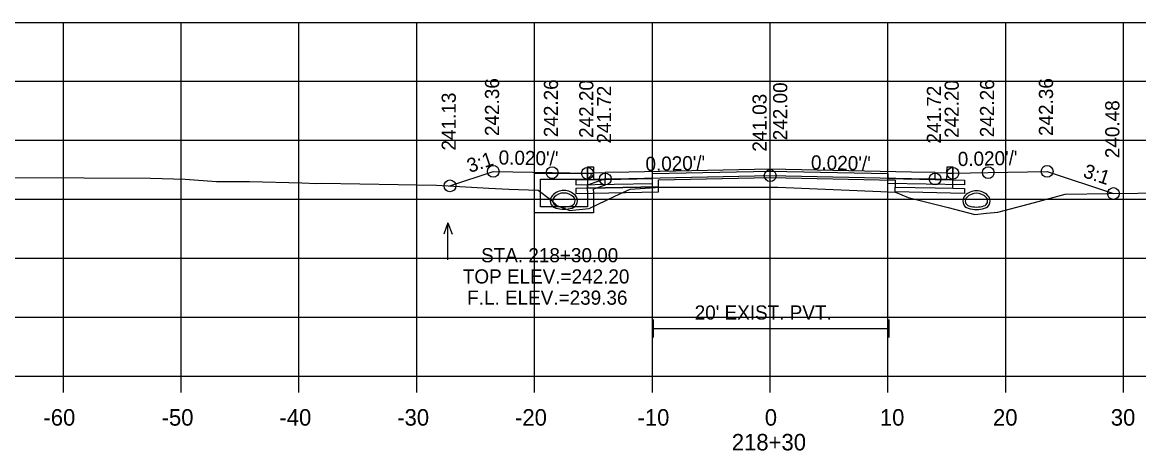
# Model space of a CAD drawing. Extents: x 1369627 to 1374022, y 380035 to 398173.
# Drawn here: x 1371475.4 to 1371570.1, y 384109.9 to 384146.2 of the extents above; entities that cross this region are included whole.
import ezdxf

# ---------------------------------------------------------------- set-up
doc = ezdxf.new("R2010")
doc.units = 0
for name, color, linetype in [('Default', 7, 'Continuous'), ('R_Alt Surface', 7, 'Continuous'), ('R_Axis', 7, 'Continuous'), ('R_Axis Annot', 7, 'Continuous'), ('R_Drive', 7, 'Continuous'), ('R_Exist Surface', 7, 'Continuous'), ('R_Fin Surface', 7, 'Continuous'), ('R_Grid', 7, 'Continuous'), ('R_No Plot', 7, 'Continuous'), ('R_Water', 7, 'Continuous'), ('R_Water Annot', 7, 'Continuous'), ('R_Xsect Elev', 7, 'Continuous'), ('R_Xsect Slope', 7, 'Continuous')]:
    doc.layers.add(name, color=color, linetype=linetype)

msp = doc.modelspace()

# ---------------------------------------------------------------- linework, layer by layer
at = {"layer": 'Default'}
for p, q in [((1371528.933, 384119.469), (1371528.933, 384120.969)), ((1371548.933, 384119.469), (1371548.933, 384120.969)), ((1371528.933, 384120.219), (1371548.933, 384120.219))]:
    msp.add_line(p, q, dxfattribs=at)
for points in [[(1371523.336, 384133.923), (1371523.836, 384133.923), (1371523.846, 384133.423), (1371524.846, 384133.443), (1371524.846, 384132.856), (1371523.346, 384132.826)], [(1371553.846, 384133.423), (1371553.856, 384133.923), (1371554.356, 384133.923), (1371554.346, 384132.826), (1371552.846, 384132.856), (1371552.846, 384133.443)]]:
    msp.add_lwpolyline(points, close=True, dxfattribs=at)
at = {"layer": 'R_Alt Surface'}
for points in [[(1371523.336, 384133.923), (1371523.346, 384132.826), (1371524.846, 384132.856), (1371528.846, 384132.936), (1371528.846, 384133.353), (1371538.846, 384133.553), (1371548.846, 384133.353), (1371548.846, 384132.936), (1371552.846, 384132.856), (1371554.346, 384132.826), (1371554.356, 384133.923)], [(1371523.336, 384133.381), (1371523.346, 384132.118), (1371524.846, 384132.148), (1371529.358, 384132.238), (1371529.358, 384132.821), (1371538.846, 384133.011), (1371549.468, 384132.798), (1371549.468, 384132.215), (1371552.846, 384132.148), (1371554.346, 384132.118), (1371554.356, 384133.381)]]:
    msp.add_lwpolyline(points, dxfattribs=at)
for points in [[(1371538.846, 384133.723), (1371526.846, 384133.483), (1371524.846, 384133.443), (1371524.846, 384132.856), (1371528.846, 384132.936), (1371528.846, 384133.353), (1371538.846, 384133.553), (1371548.846, 384133.353), (1371548.846, 384132.936), (1371552.846, 384132.856), (1371552.846, 384133.443), (1371550.846, 384133.483)], [(1371528.846, 384132.936), (1371524.846, 384132.856), (1371523.346, 384132.826), (1371522.346, 384132.806), (1371522.346, 384132.389), (1371528.846, 384132.519)], [(1371529.358, 384132.238), (1371524.846, 384132.148), (1371523.346, 384132.118), (1371522.346, 384132.098), (1371522.346, 384131.681), (1371529.358, 384131.821)], [(1371548.846, 384132.936), (1371552.846, 384132.856), (1371554.346, 384132.826), (1371555.346, 384132.806), (1371555.346, 384132.389), (1371548.846, 384132.519)], [(1371549.468, 384132.215), (1371552.846, 384132.148), (1371554.346, 384132.118), (1371555.346, 384132.098), (1371555.346, 384131.681), (1371549.468, 384131.798)]]:
    msp.add_lwpolyline(points, close=True, dxfattribs=at)
at = {"layer": 'R_Axis'}
for p, q in [((1371388.846, 384116.181), (1371688.846, 384116.181)), ((1371478.846, 384114.781), (1371478.846, 384116.181)), ((1371488.846, 384114.781), (1371488.846, 384116.181)), ((1371498.846, 384114.781), (1371498.846, 384116.181)), ((1371508.846, 384114.781), (1371508.846, 384116.181)), ((1371518.846, 384114.781), (1371518.846, 384116.181)), ((1371528.846, 384114.781), (1371528.846, 384116.181)), ((1371538.846, 384114.781), (1371538.846, 384116.181)), ((1371548.846, 384114.781), (1371548.846, 384116.181)), ((1371558.846, 384114.781), (1371558.846, 384116.181)), ((1371568.846, 384114.781), (1371568.846, 384116.181))]:
    msp.add_line(p, q, dxfattribs=at)
at = {"layer": 'R_Drive'}
for centre, radius, start, end in [((1371520.823, 384131.05), 0.646, 136.35152, 253.95293), ((1371520.823, 384131.05), 0.646, 136.35152, 253.95293), ((1371521.336, 384130.561), 1.354, 43.64848, 136.35152), ((1371521.336, 384130.561), 1.354, 43.64848, 136.35152), ((1371520.823, 384131.05), 0.438, 136.35152, 253.95293), ((1371520.823, 384131.05), 0.438, 136.35152, 253.95293), ((1371521.336, 384130.561), 1.146, 43.64848, 136.35152), ((1371521.336, 384130.561), 1.146, 43.64848, 136.35152), ((1371521.848, 384131.05), 0.438, 286.04707, 43.64848), ((1371521.848, 384131.05), 0.438, 286.04707, 43.64848), ((1371521.848, 384131.05), 0.646, 286.04707, 43.64848), ((1371521.848, 384131.05), 0.646, 286.04707, 43.64848), ((1371555.843, 384131.031), 0.646, 136.35152, 253.95293), ((1371556.356, 384130.542), 1.354, 43.64848, 136.35152), ((1371555.843, 384131.031), 0.438, 136.35152, 253.95293), ((1371556.356, 384130.542), 1.146, 43.64848, 136.35152), ((1371556.868, 384131.031), 0.438, 286.04707, 43.64848), ((1371556.868, 384131.031), 0.646, 286.04707, 43.64848), ((1371521.336, 384132.832), 2.5, 253.95293, 286.04707), ((1371521.336, 384132.832), 2.5, 253.95293, 286.04707), ((1371521.336, 384132.832), 2.292, 253.95293, 286.04707), ((1371521.336, 384132.832), 2.292, 253.95293, 286.04707), ((1371556.356, 384132.813), 2.5, 253.95293, 286.04707), ((1371556.356, 384132.813), 2.292, 253.95293, 286.04707)]:
    msp.add_arc(centre, radius, start, end, dxfattribs=at)
at = {"layer": 'R_Exist Surface'}
msp.add_lwpolyline([(1371460.93, 384133.052), (1371480.608, 384132.995), (1371486.239, 384132.978), (1371489.193, 384132.892), (1371491.852, 384132.675), (1371494.248, 384132.694), (1371494.651, 384132.687), (1371499.078, 384132.571), (1371500.357, 384132.52), (1371500.761, 384132.53), (1371510.527, 384132.38), (1371514.966, 384132.129), (1371516.65, 384132.025), (1371519.149, 384131.96), (1371520.194, 384131.15), (1371520.736, 384130.637), (1371521.706, 384130.269), (1371521.815, 384130.227), (1371522.351, 384130.286), (1371523.471, 384130.394), (1371525.668, 384131.437), (1371526.954, 384132.045), (1371529.096, 384132.177), (1371529.358, 384132.202), (1371530.403, 384132.206), (1371539.505, 384132.212), (1371548.246, 384131.832), (1371549.468, 384131.779), (1371549.48, 384131.774), (1371550.556, 384131.333), (1371553.949, 384130.473), (1371556.22, 384129.89), (1371557.22, 384129.988), (1371558.178, 384130.085), (1371561.283, 384130.916), (1371563.876, 384131.601), (1371567.587, 384131.659), (1371574.957, 384131.752)], dxfattribs=at)
at = {"layer": 'R_Fin Surface'}
msp.add_lwpolyline([(1371511.66, 384132.316), (1371515.336, 384133.541), (1371520.336, 384133.441), (1371523.336, 384133.381), (1371523.836, 384133.381), (1371523.846, 384132.881), (1371524.846, 384132.901), (1371526.846, 384132.941), (1371538.846, 384133.181), (1371550.846, 384132.941), (1371552.846, 384132.901), (1371553.846, 384132.881), (1371553.856, 384133.381), (1371554.356, 384133.381), (1371557.356, 384133.441), (1371562.356, 384133.541), (1371567.988, 384131.664)], dxfattribs=at)
at = {"layer": 'R_Grid'}
for p, q in [((1371388.846, 384146.181), (1371688.846, 384146.181)), ((1371478.846, 384116.181), (1371478.846, 384146.181)), ((1371488.846, 384116.181), (1371488.846, 384146.181)), ((1371498.846, 384116.181), (1371498.846, 384146.181)), ((1371508.846, 384116.181), (1371508.846, 384146.181)), ((1371518.846, 384116.181), (1371518.846, 384146.181)), ((1371528.846, 384116.181), (1371528.846, 384146.181)), ((1371538.846, 384116.181), (1371538.846, 384146.181)), ((1371548.846, 384116.181), (1371548.846, 384146.181)), ((1371558.846, 384116.181), (1371558.846, 384146.181)), ((1371568.846, 384116.181), (1371568.846, 384146.181)), ((1371388.846, 384141.181), (1371688.846, 384141.181)), ((1371388.846, 384136.181), (1371688.846, 384136.181)), ((1371388.846, 384131.181), (1371688.846, 384131.181)), ((1371388.846, 384126.181), (1371688.846, 384126.181)), ((1371388.846, 384121.181), (1371688.846, 384121.181)), ((1371388.846, 384116.181), (1371688.846, 384116.181))]:
    msp.add_line(p, q, dxfattribs=at)
at = {"layer": 'R_No Plot'}
for centre in [(1371515.336, 384133.541), (1371562.356, 384133.541), (1371520.336, 384133.441), (1371523.336, 384133.381), (1371524.846, 384132.901), (1371538.846, 384133.181), (1371552.846, 384132.901), (1371554.356, 384133.381), (1371557.356, 384133.441), (1371511.66, 384132.316), (1371567.988, 384131.664)]:
    msp.add_circle(centre, 0.5, dxfattribs=at)
at = {"layer": 'R_Water'}
for p, q in [((1371518.836, 384133.381), (1371523.586, 384133.381)), ((1371518.836, 384131.881), (1371518.836, 384133.381)), ((1371523.668, 384133.216), (1371523.336, 384132.881)), ((1371523.668, 384133.216), (1371523.586, 384133.381)), ((1371519.336, 384131.881), (1371519.336, 384132.881)), ((1371519.336, 384132.881), (1371523.336, 384132.881)), ((1371524.836, 384132.901), (1371523.336, 384132.381)), ((1371523.336, 384131.881), (1371523.336, 384132.381)), ((1371524.836, 384132.372), (1371523.836, 384132.025)), ((1371523.836, 384131.881), (1371523.836, 384132.025))]:
    msp.add_line(p, q, dxfattribs=at)
for points in [[(1371524.836, 384132.372), (1371524.836, 384132.901)], [(1371523.836, 384131.881), (1371523.836, 384130.04), (1371521.336, 384130.04), (1371518.836, 384130.04), (1371518.836, 384131.881)], [(1371523.336, 384131.881), (1371523.336, 384130.54), (1371521.336, 384130.54), (1371519.336, 384130.54), (1371519.336, 384131.881)]]:
    msp.add_lwpolyline(points, dxfattribs=at)
at = {"layer": 'R_Water Annot'}
for p, q in [((1371511.496, 384129.187), (1371511.146, 384128.225)), ((1371511.496, 384126.045), (1371511.496, 384129.187)), ((1371511.496, 384129.187), (1371511.846, 384128.225))]:
    msp.add_line(p, q, dxfattribs=at)
at = {"layer": 'R_Xsect Elev'}
msp.add_line((1371538.846, 384132.212), (1371538.846, 384142.212), dxfattribs=at)

# ---------------------------------------------------------------- texts
at = {"layer": 'R_Axis Annot'}
for s, height, p in [("20' EXIST. PVT.", 1.2, (1371532.436, 384120.976)), ('-60', 1.4, (1371477.154, 384111.981)), ('-50', 1.4, (1371487.187, 384111.981)), ('-40', 1.4, (1371497.187, 384111.981)), ('-30', 1.4, (1371507.187, 384111.981)), ('-20', 1.4, (1371517.187, 384111.981)), ('-10', 1.4, (1371527.584, 384111.981)), ('0', 1.4, (1371538.388, 384111.981)), ('10', 1.4, (1371548.157, 384111.981)), ('20', 1.4, (1371557.76, 384111.981)), ('30', 1.4, (1371567.76, 384111.981)), ('218+30', 1.4, (1371535.588, 384109.881))]:
    msp.add_text(s, height=height, dxfattribs=at).set_placement(p)
at = {"layer": 'R_Water Annot'}
for s, p in [('STA. 218+30.00', (1371514.306, 384125.835)), ('TOP ELEV.=242.20', (1371512.757, 384124.035)), ('F.L. ELEV.=239.36', (1371513.125, 384122.235))]:
    msp.add_text(s, height=1.2, dxfattribs=at).set_placement(p)
at = {"layer": 'R_Xsect Elev'}
for s, p in [('242.36', (1371515.836, 384136.541)), ('242.26', (1371520.836, 384136.441)), ('242.20', (1371523.836, 384136.381)), ('241.72', (1371525.346, 384135.901)), ('242.00', (1371540.297, 384136.181)), ('241.72', (1371553.346, 384135.901)), ('242.20', (1371554.856, 384136.381)), ('242.26', (1371557.856, 384136.441)), ('242.36', (1371562.856, 384136.541)), ('241.13', (1371512.16, 384135.316)), ('241.03', (1371538.546, 384135.212)), ('240.48', (1371568.488, 384134.664))]:
    msp.add_text(s, height=1.2, rotation=90, dxfattribs=at).set_placement(p)
at = {"layer": 'R_Xsect Slope'}
for s, rotation, p in [('3:1', 18.43323, (1371513.34, 384133.403)), ("0.020'/'", 358.85424, (1371515.786, 384134.132)), ("0.020'/'", 1.14576, (1371554.782, 384133.989)), ("0.020'/'", 1.14576, (1371528.272, 384133.569)), ("0.020'/'", 358.85424, (1371542.296, 384133.712)), ('3:1', 341.56677, (1371565.33, 384133.077))]:
    msp.add_text(s, height=1.2, rotation=rotation, dxfattribs=at).set_placement(p)

doc.saveas('drawing.dxf')
